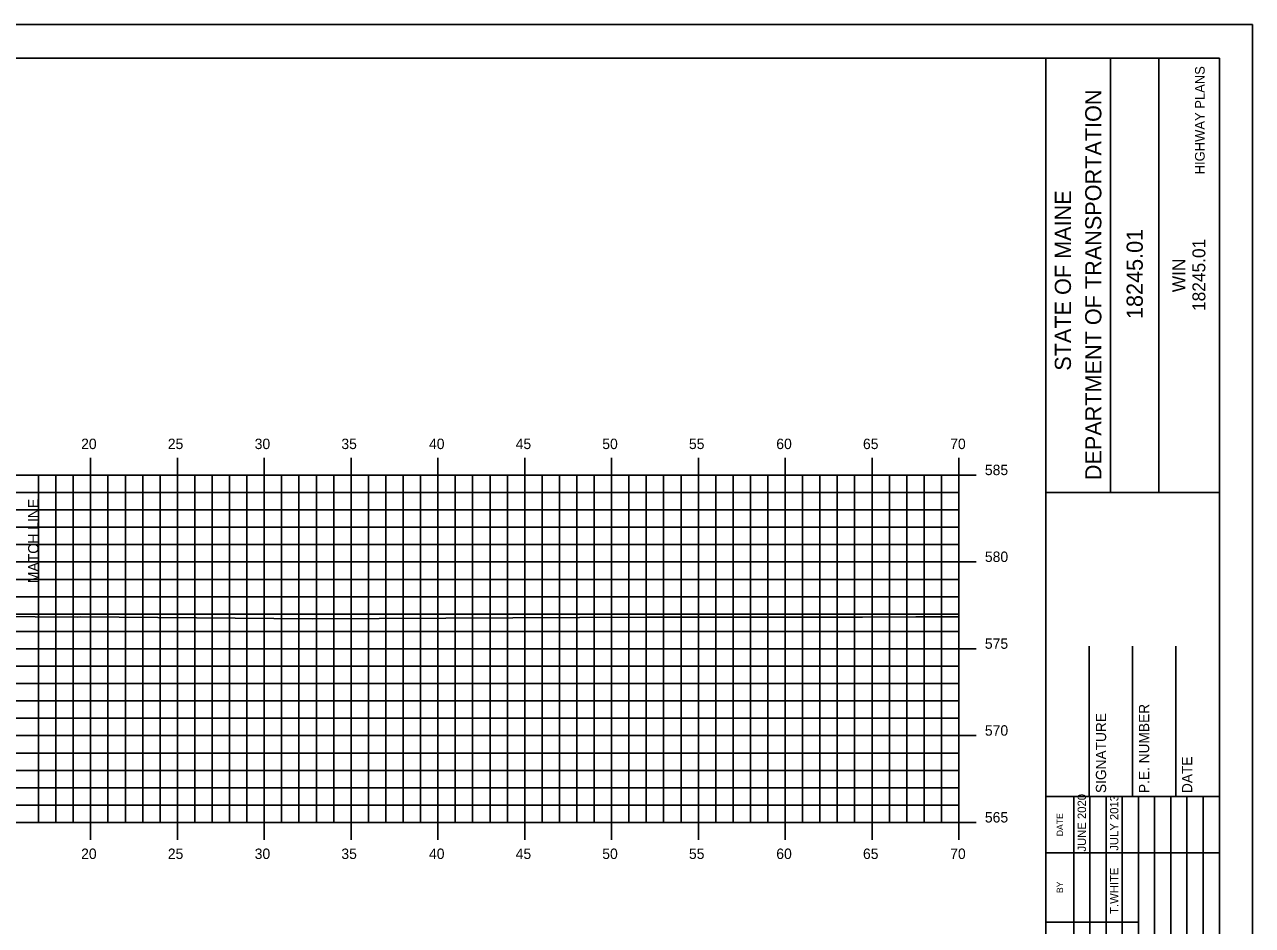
# Model space of a CAD drawing. Extents: x 1048345 to 1048515, y 781148 to 781258.
# Drawn here: x 1048444 to 1048514.7, y 781206.3 to 781258.2 of the extents above; entities that cross this region are included whole.
import ezdxf

# ---------------------------------------------------------------- set-up
doc = ezdxf.new("R2010")
doc.units = 0
for name, color, linetype in [('BORDER', 7, 'Continuous'), ('E_ROW_Line', 7, 'Continuous'), ('H_V ANNOTATION', 7, 'Continuous'), ('HIGHWAY_TITLE', 7, 'Continuous'), ('MAJOR', 7, 'Continuous'), ('MINOR', 7, 'Continuous'), ('PLOT BOUNDARY', 7, 'Continuous'), ('S_Roadway_Centerline', 7, 'Continuous')]:
    doc.layers.add(name, color=color, linetype=linetype)

msp = doc.modelspace()

# ---------------------------------------------------------------- linework, layer by layer
at = {"layer": 'BORDER'}
for p, q in [((1048502.833, 781151.252), (1048502.833, 781256.252)), ((1048506.561, 781231.249), (1048506.561, 781256.249)), ((1048509.356, 781231.249), (1048509.356, 781256.249)), ((1048502.833, 781231.246), (1048512.833, 781231.246)), ((1048505.333, 781213.755), (1048505.333, 781222.403)), ((1048507.833, 781213.755), (1048507.833, 781222.403)), ((1048510.333, 781213.755), (1048510.333, 781222.403)), ((1048502.833, 781213.755), (1048512.833, 781213.755))]:
    msp.add_line(p, q, dxfattribs=at)
msp.add_lwpolyline([(1048352.833, 781151.252), (1048512.833, 781151.252), (1048512.833, 781256.252), (1048352.833, 781256.252)], close=True, dxfattribs=at)
for points in [[(1048504.447, 781210.505), (1048504.447, 781213.755)], [(1048505.38, 781196.258), (1048505.38, 781213.755)], [(1048506.312, 781213.755), (1048506.312, 781196.258)], [(1048507.243, 781196.258), (1048507.243, 781213.755)], [(1048508.175, 781196.258), (1048508.175, 781213.755)], [(1048509.107, 781196.258), (1048509.107, 781213.755)], [(1048510.038, 781196.258), (1048510.038, 781213.755)], [(1048510.97, 781196.258), (1048510.97, 781213.755)], [(1048511.902, 781196.258), (1048511.902, 781213.755)], [(1048504.448, 781196.258), (1048504.448, 781213.049)], [(1048502.833, 781210.505), (1048512.833, 781210.505)], [(1048502.833, 781206.505), (1048504.448, 781206.505)], [(1048504.447, 781206.505), (1048508.174, 781206.505)]]:
    msp.add_lwpolyline(points, dxfattribs=at)
at = {"layer": 'MAJOR'}
for p, q in [((1048447.832, 781233.254), (1048447.832, 781232.252)), ((1048452.832, 781233.254), (1048452.832, 781232.252)), ((1048457.832, 781233.254), (1048457.832, 781232.252)), ((1048462.832, 781233.254), (1048462.832, 781232.252)), ((1048467.832, 781233.254), (1048467.832, 781232.252)), ((1048472.832, 781233.254), (1048472.832, 781232.252)), ((1048477.832, 781233.254), (1048477.832, 781232.252)), ((1048482.832, 781233.254), (1048482.832, 781232.252)), ((1048487.832, 781233.254), (1048487.832, 781232.252)), ((1048492.832, 781233.254), (1048492.832, 781232.252)), ((1048497.832, 781233.254), (1048497.832, 781232.252)), ((1048357.832, 781232.252), (1048497.832, 781232.252)), ((1048357.832, 781232.252), (1048497.832, 781232.252)), ((1048447.832, 781212.252), (1048447.832, 781232.252)), ((1048452.832, 781212.252), (1048452.832, 781232.252)), ((1048457.832, 781212.252), (1048457.832, 781232.252)), ((1048462.832, 781212.252), (1048462.832, 781232.252)), ((1048467.832, 781212.252), (1048467.832, 781232.252)), ((1048472.832, 781212.252), (1048472.832, 781232.252)), ((1048477.832, 781212.252), (1048477.832, 781232.252)), ((1048482.832, 781212.252), (1048482.832, 781232.252)), ((1048487.832, 781212.252), (1048487.832, 781232.252)), ((1048492.832, 781212.252), (1048492.832, 781232.252)), ((1048498.834, 781232.252), (1048496.83, 781232.252)), ((1048497.832, 781212.252), (1048497.832, 781232.252)), ((1048497.832, 781212.252), (1048497.832, 781232.252)), ((1048357.832, 781227.252), (1048497.832, 781227.252)), ((1048498.834, 781227.252), (1048496.83, 781227.252)), ((1048357.832, 781222.252), (1048497.832, 781222.252)), ((1048498.834, 781222.252), (1048496.83, 781222.252)), ((1048357.832, 781217.252), (1048497.832, 781217.252)), ((1048498.834, 781217.252), (1048496.83, 781217.252)), ((1048357.832, 781212.252), (1048497.832, 781212.252)), ((1048357.832, 781212.252), (1048497.832, 781212.252)), ((1048447.832, 781211.25), (1048447.832, 781212.252)), ((1048452.832, 781211.25), (1048452.832, 781212.252)), ((1048457.832, 781211.25), (1048457.832, 781212.252)), ((1048462.832, 781211.25), (1048462.832, 781212.252)), ((1048467.832, 781211.25), (1048467.832, 781212.252)), ((1048472.832, 781211.25), (1048472.832, 781212.252)), ((1048477.832, 781211.25), (1048477.832, 781212.252)), ((1048482.832, 781211.25), (1048482.832, 781212.252)), ((1048487.832, 781211.25), (1048487.832, 781212.252)), ((1048492.832, 781211.25), (1048492.832, 781212.252)), ((1048498.834, 781212.252), (1048496.83, 781212.252)), ((1048497.832, 781211.25), (1048497.832, 781212.252))]:
    msp.add_line(p, q, dxfattribs=at)
at = {"layer": 'MINOR'}
for p, q in [((1048444.832, 781212.252), (1048444.832, 781232.252)), ((1048445.832, 781212.252), (1048445.832, 781232.252)), ((1048446.832, 781212.252), (1048446.832, 781232.252)), ((1048448.832, 781212.252), (1048448.832, 781232.252)), ((1048449.832, 781212.252), (1048449.832, 781232.252)), ((1048450.832, 781212.252), (1048450.832, 781232.252)), ((1048451.832, 781212.252), (1048451.832, 781232.252)), ((1048453.832, 781212.252), (1048453.832, 781232.252)), ((1048454.832, 781212.252), (1048454.832, 781232.252)), ((1048455.832, 781212.252), (1048455.832, 781232.252)), ((1048456.832, 781212.252), (1048456.832, 781232.252)), ((1048458.832, 781212.252), (1048458.832, 781232.252)), ((1048459.832, 781212.252), (1048459.832, 781232.252)), ((1048460.832, 781212.252), (1048460.832, 781232.252)), ((1048461.832, 781212.252), (1048461.832, 781232.252)), ((1048463.832, 781212.252), (1048463.832, 781232.252)), ((1048464.832, 781212.252), (1048464.832, 781232.252)), ((1048465.832, 781212.252), (1048465.832, 781232.252)), ((1048466.832, 781212.252), (1048466.832, 781232.252)), ((1048468.832, 781212.252), (1048468.832, 781232.252)), ((1048469.832, 781212.252), (1048469.832, 781232.252)), ((1048470.832, 781212.252), (1048470.832, 781232.252)), ((1048471.832, 781212.252), (1048471.832, 781232.252)), ((1048473.832, 781212.252), (1048473.832, 781232.252)), ((1048474.832, 781212.252), (1048474.832, 781232.252)), ((1048475.832, 781212.252), (1048475.832, 781232.252)), ((1048476.832, 781212.252), (1048476.832, 781232.252)), ((1048478.832, 781212.252), (1048478.832, 781232.252)), ((1048479.832, 781212.252), (1048479.832, 781232.252)), ((1048480.832, 781212.252), (1048480.832, 781232.252)), ((1048481.832, 781212.252), (1048481.832, 781232.252)), ((1048483.832, 781212.252), (1048483.832, 781232.252)), ((1048484.832, 781212.252), (1048484.832, 781232.252)), ((1048485.832, 781212.252), (1048485.832, 781232.252)), ((1048486.832, 781212.252), (1048486.832, 781232.252)), ((1048488.832, 781212.252), (1048488.832, 781232.252)), ((1048489.832, 781212.252), (1048489.832, 781232.252)), ((1048490.832, 781212.252), (1048490.832, 781232.252)), ((1048491.832, 781212.252), (1048491.832, 781232.252)), ((1048493.832, 781212.252), (1048493.832, 781232.252)), ((1048494.832, 781212.252), (1048494.832, 781232.252)), ((1048495.832, 781212.252), (1048495.832, 781232.252)), ((1048496.832, 781212.252), (1048496.832, 781232.252)), ((1048357.832, 781231.252), (1048497.832, 781231.252)), ((1048497.832, 781231.252), (1048496.83, 781231.252)), ((1048357.832, 781230.252), (1048497.832, 781230.252)), ((1048497.832, 781230.252), (1048496.83, 781230.252)), ((1048357.832, 781229.252), (1048497.832, 781229.252)), ((1048497.832, 781229.252), (1048496.83, 781229.252)), ((1048357.832, 781228.252), (1048497.832, 781228.252)), ((1048497.832, 781228.252), (1048496.83, 781228.252)), ((1048357.832, 781226.252), (1048497.832, 781226.252)), ((1048497.832, 781226.252), (1048496.83, 781226.252)), ((1048357.832, 781225.252), (1048497.832, 781225.252)), ((1048497.832, 781225.252), (1048496.83, 781225.252)), ((1048357.832, 781224.252), (1048497.832, 781224.252)), ((1048497.832, 781224.252), (1048496.83, 781224.252)), ((1048357.832, 781223.252), (1048497.832, 781223.252)), ((1048497.832, 781223.252), (1048496.83, 781223.252)), ((1048357.832, 781221.252), (1048497.832, 781221.252)), ((1048497.832, 781221.252), (1048496.83, 781221.252)), ((1048357.832, 781220.252), (1048497.832, 781220.252)), ((1048497.832, 781220.252), (1048496.83, 781220.252)), ((1048357.832, 781219.252), (1048497.832, 781219.252)), ((1048497.832, 781219.252), (1048496.83, 781219.252)), ((1048357.832, 781218.252), (1048497.832, 781218.252)), ((1048497.832, 781218.252), (1048496.83, 781218.252)), ((1048357.832, 781216.252), (1048497.832, 781216.252)), ((1048497.832, 781216.252), (1048496.83, 781216.252)), ((1048357.832, 781215.252), (1048497.832, 781215.252)), ((1048497.832, 781215.252), (1048496.83, 781215.252)), ((1048357.832, 781214.252), (1048497.832, 781214.252)), ((1048497.832, 781214.252), (1048496.83, 781214.252)), ((1048357.832, 781213.252), (1048497.832, 781213.252)), ((1048497.832, 781213.252), (1048496.83, 781213.252))]:
    msp.add_line(p, q, dxfattribs=at)
at = {"layer": 'PLOT BOUNDARY'}
msp.add_lwpolyline([(1048344.739, 781148.193), (1048514.739, 781148.193), (1048514.739, 781258.193), (1048344.739, 781258.193)], close=True, dxfattribs=at)
at = {"layer": 'S_Roadway_Centerline'}
msp.add_lwpolyline([(1048439.732, 781224.125), (1048447.103, 781224.075), (1048447.245, 781224.084), (1048460.617, 781223.987), (1048479.825, 781224.072), (1048490.397, 781224.083), (1048492.285, 781224.075), (1048495.352, 781224.095), (1048497.832, 781224.095)], dxfattribs=at)

# ---------------------------------------------------------------- texts
at = {"layer": 'BORDER'}
for s, height, p in [('DEPARTMENT OF TRANSPORTATION', 0.93176, (1048506.039, 781231.958)), ('STATE OF MAINE', 0.93176, (1048504.288, 781238.264)), ('18245.01', 0.9318, (1048508.424, 781241.237)), ('18245.01', 0.7453, (1048512.028, 781241.703)), ('WIN', 0.7453, (1048510.869, 781242.782)), ('P.E. NUMBER', 0.59055, (1048508.793, 781213.947)), ('SIGNATURE', 0.5906, (1048506.313, 781213.947)), ('DATE', 0.5906, (1048511.274, 781213.947)), ('JUNE 2020', 0.4845, (1048505.155, 781210.58)), ('JULY 2013', 0.4845, (1048507.019, 781210.627)), ('DATE', 0.3714, (1048503.837, 781211.461)), ('T.WHITE', 0.4845, (1048507.019, 781206.99)), ('BY', 0.3714, (1048503.837, 781208.19))]:
    msp.add_text(s, height=height, rotation=90, dxfattribs=at).set_placement(p)
at = {"layer": 'E_ROW_Line'}
msp.add_text('MATCH LINE', height=0.6, rotation=90, dxfattribs=at).set_placement((1048444.832, 781226.028))
at = {"layer": 'H_V ANNOTATION'}
for s, p in [('20', (1048447.286, 781233.752)), ('25', (1048452.278, 781233.752)), ('30', (1048457.281, 781233.752)), ('35', (1048462.273, 781233.752)), ('40', (1048467.319, 781233.752)), ('45', (1048472.311, 781233.752)), ('50', (1048477.297, 781233.752)), ('55', (1048482.289, 781233.752)), ('60', (1048487.319, 781233.752)), ('65', (1048492.311, 781233.752)), ('70', (1048497.334, 781233.752)), ('585', (1048499.332, 781232.252)), ('580', (1048499.332, 781227.252)), ('575', (1048499.332, 781222.252)), ('570', (1048499.332, 781217.252)), ('565', (1048499.332, 781212.252)), ('20', (1048447.286, 781210.152)), ('25', (1048452.278, 781210.152)), ('30', (1048457.281, 781210.152)), ('35', (1048462.273, 781210.152)), ('40', (1048467.319, 781210.152)), ('45', (1048472.311, 781210.152)), ('50', (1048477.297, 781210.152)), ('55', (1048482.289, 781210.152)), ('60', (1048487.319, 781210.152)), ('65', (1048492.311, 781210.152)), ('70', (1048497.334, 781210.152))]:
    msp.add_text(s, height=0.6, dxfattribs=at).set_placement(p)
at = {"layer": 'HIGHWAY_TITLE'}
msp.add_text('HIGHWAY PLANS', height=0.55901, rotation=90, dxfattribs=at).set_placement((1048511.991, 781249.568))
at = {"layer": 'S_Roadway_Centerline'}
for s, p in [('C', (1048479.82, 781224.072)), ('L', (1048479.825, 781224.064))]:
    msp.add_text(s, height=0.0146, dxfattribs=at).set_placement(p)

doc.saveas('drawing.dxf')
